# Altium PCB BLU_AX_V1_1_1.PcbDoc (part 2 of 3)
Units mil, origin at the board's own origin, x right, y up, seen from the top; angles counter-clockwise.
Board outline 2623.2 x 4215 mil, 6 copper layers (Top Layer, GND1, PWR, Signal Inner, GND2, Bottom Layer), stack 76.535 mil thick; 238 components, 119 nets, 699 pads, 786 vias.
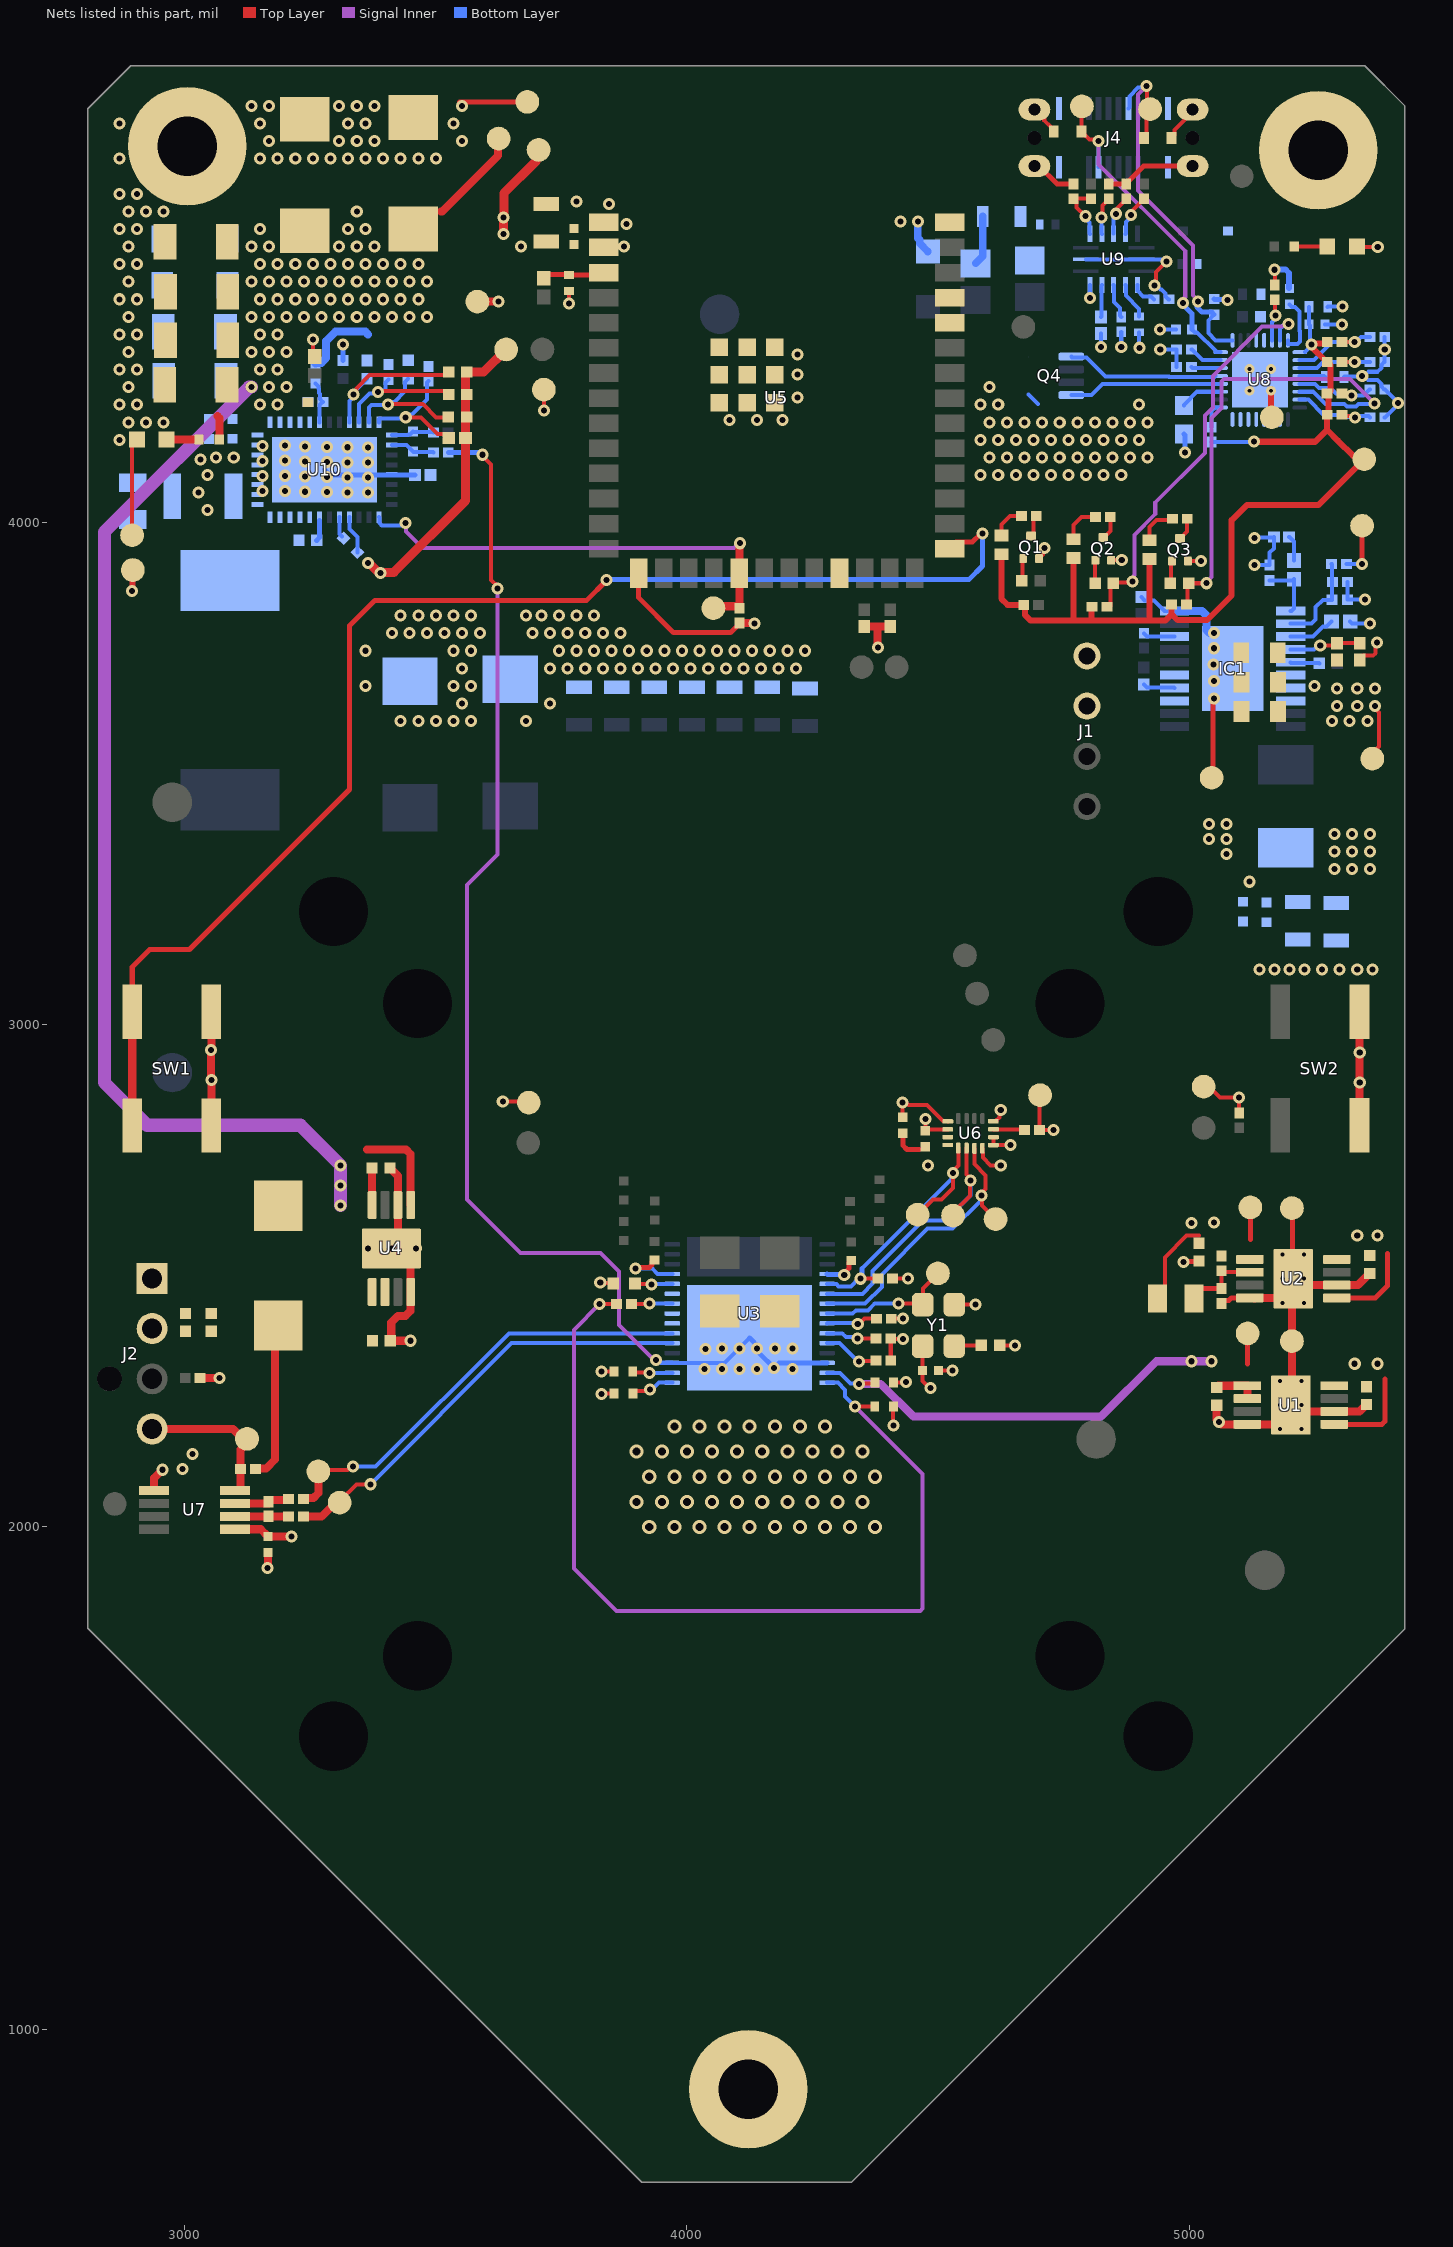
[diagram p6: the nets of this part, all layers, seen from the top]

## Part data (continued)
R4: library part CMP-x00008-3, "Fixed Resistor, Metal Glaze/thick Film, 0.1W, 2200ohm, 75V, 1% +/-Tol, 100ppm/Cel, Surface Mount, 0402", Manufacturer="KOA Speer", Package=0402, Rating=100mW, Template=KS_0402
R5 R6 R20 R29 R30 R31 R38 R80: library part CMP-x00150-1, "Fixed Resistor, Metal Glaze/thick Film, 0.1W, 10000ohm, 75V, 1% +/-Tol, 100ppm/Cel, Surface Mount, 0402"
R9 R35 R36 R37 R76 R78 R79 R81 R83: library part CMP-x00147-1, "Metal Glaze/thick Film, 0ohm, Surface Mount, 0402"
R21: library part CMP-2002-04371-1, Manufacturer="KOA Speer"
R22 R23: library part CMP-2002-03812-1, Manufacturer="KOA Speer"
R24 R27 R56 R57 R58 R62 R67: library part CMP-009-00227-1, "Fixed Resistor, Metal Glaze/thick Film, 0.1W, 10000ohm, 75V, 5% +/-Tol, 200ppm/Cel, Surface Mount, 0402", Package=0402, Rating=1/10W
R25 R26: library part CMP-x00174-1, "Fixed Resistor, Metal Glaze/thick Film, 0.1W, 100ohm, 75V, 1% +/-Tol, 100ppm/Cel, Surface Mount, 0402"
R28 R68: library part CMP-x00164-1, "Fixed Resistor, Metal Glaze/thick Film, 0.1W, 5600ohm, 75V, 1% +/-Tol, 100ppm/Cel, Surface Mount, 0402"
R32 R33 R34 R54: library part CMP-009-00229-1, "Fixed Resistor, Metal Glaze/thick Film, 0.1W, 23200ohm, 75V, 1% +/-Tol, 100ppm/Cel, Surface Mount, 0402", Package=0402, Rating=1/10W
R39: library part CMP-2002-04376-1, Manufacturer="KOA Speer", Part Number=RK73H1ETTP33R2F
R40 R43 R48 R49 R50 R51 R59 R60 R64 R65 R66: library part CMP-x00162-1, "Fixed Resistor, Metal Glaze/thick Film, 0.1W, 100000ohm, 75V, 1% +/-Tol, 100ppm/Cel, Surface Mount, 0402"
R41: library part CMP-2002-04506-1, Manufacturer="KOA Speer"
R42: library part CMP-2002-04318-1, Manufacturer="KOA Speer"
R44: library part CMP-2002-04177-1, Manufacturer="KOA Speer"
R47 R61: library part CMP-x00015-3, "Fixed Resistor, Thin Film, 0.063W, 1000ohm, 50V, 0.1% +/-Tol, 25ppm/Cel, Surface Mount, 0402", Manufacturer=Panasonic, Package=0402, Rating=63mW, Template=PS_0402
R52 R55: library part CMP-x00172-1, "Fixed Resistor, Metal Glaze/thick Film, 0.1W, 4990ohm, 75V, 1% +/-Tol, 100ppm/Cel, Surface Mount, 0402"
R53: library part CMP-x00173-1, "Fixed Resistor, Metal Glaze/thick Film, 0.1W, 118000ohm, 75V, 1% +/-Tol, 100ppm/Cel, Surface Mount, 0402"
R63: library part CMP-x00167-1, "Fixed Resistor, Metal Glaze/thick Film, 0.25W, 3.6ohm, 150V, 1% +/-Tol, 200ppm/Cel, Surface Mount, 0805"
R69: library part CMP-2002-03957-1, Manufacturer="KOA Speer"
R70: library part CMP-x00151-1, "BOM UPDATE 25.5K (NEW) RESISTOR FROM 11.7K (OLD) /  / NEW: RK73H1ETTP2552F"
R71: library part CMP-x00144-1, "Fixed Resistor, Metal Glaze/thick Film, 0.1W, 10ohm, 75V, 1% +/-Tol, 100ppm/Cel, Surface Mount, 0402"
R72: library part CMP-x00142-1, "Fixed Resistor, Metal Glaze/thick Film, 0.5W, 1ohm, 200V, 1% +/-Tol, 200ppm/Cel, Surface Mount, 1210", Manufacturer="KOA Speer", Package=1210, Template=KO_0402
R73: library part CMP-2002-04015-1, "BOM UPDATE 4.32K (NEW) RESISTOR FROM 37.4K (OLD) /  / NEW: RK73H1ETTP4321F", Manufacturer="KOA Speer", Part Number=RK73H1ETTP3741F
R74 R77: library part CMP-x00154-1, "Fixed Resistor, Metal Glaze/thick Film, 0.1W, 49.9ohm, 75V, 1% +/-Tol, 100ppm/Cel, Surface Mount, 0402"
R75: library part CMP-2002-04539-1, Manufacturer="KOA Speer"
R82: library part CMP-x00145-1, "Fixed Resistor, Metal Glaze/thick Film, 0.1W, 68100ohm, 75V, 1% +/-Tol, 100ppm/Cel, Surface Mount, 0402"
R84: library part CMP-x00149-1, "Fixed Resistor, Metal Glaze/thick Film, 0.1W, 14700ohm, 75V, 1% +/-Tol, 100ppm/Cel, Surface Mount, 0402"
RJ1: library part CMP-009-00121-2, Max Operating Temperature=155°C, Min Operating Temperature=-55°C
SW1 SW2: library part CMP-011-00029-1, "No Description Available", Mfr_Name=Omron
TP1 TP2 TP12 TP13 TP14 TP16 TP17 TP18 TP19 TP20 TP21 TP22 TP23 TP24 TP25 TP26 TP27 TP28 TP29 TP30 TP31 TP32 TP33 TP34 TP35 TP36 TP37 TP38 TP39 TP40: library part CMP-001-0086-3, "digital shovel test point"
TP3 TP4 TP5 TP6 TP7 TP8 TP9 TP10 TP11 TP15 TP41: library part CMP-001-0086-4, "digital shovel test point"
TVS3 TVS4: library part CMP-x00209-4, "Trans Voltage Suppressor Diode, 180W, 5V V(RWM), Unidirectional, 1 Element, Silicon", Manufacturer=Nexperia, Package=SOD_523_2, Template=NX_SOD_523_2
U1: library part CMP-x00161-1, "Adjustable- and fixed-output, 1-A, 16-V, positive-voltage low-dropout (LDO) linear regulator 8-HVSSOP -40 to 125"
U2: library part CMP-x00158-1, "Adjustable Positive Standard Regulator, 0.8V Min, 13.6V Max, PDSO8"
U3: library part CMP-x00104-5, "BCM1370 Miner Chip", Manufacturer=Bitmain, Package=QFN32, Template=BM_QFN32
U4: library part CMP-x00161-4, "Adjustable- and fixed-output, 1-A, 16-V, positive-voltage low-dropout (LDO) linear regulator 8-HVSSOP -40 to 125", Manufacturer=TI, Package=HVSSOP, Template=TI_HVSSOP
U5: library part CMP-226-000000-01-A-2, "No Description Available", Mfr_Name="Espressif Systems"
U6: library part CMP-x00133-2, "74AVC4T774 - 4-bit dual supply translating transceiver; 3-state", Manufacturer=Nexperia, Package=XQFN_16, Template=NX_XQFN_16
U7: library part CMP-x00137-1, "Serial Switch/Digital Sensor, 11 Bit(s), 2Cel, Square, Surface Mount", Manufacturer=Microchip, Package=TSSOP_8, Template=MC_TSSOP_8
U8: library part CMP-x00105-1, "Sink-only USB Type-C® and USB Power Delivery (PD) controller with no firmware development required 32-VQFN -40 to 125", Manufacturer="Texas Instruments", Package=32-VQFN, Template=TI_VQFN_32
U9: library part CMP-x00113-1, "28V/6A Efuse With True Rcb & Frs", Manufacturer=Littelfuse, Package=QFN_16, Template=LF_QFN_16
U10: library part CMP-x00141-6, "Switching Regulator, Current-mode, 40A, 1500kHz Switching Freq-Max, PQCC40"
Y1: library part CMP-x00169-1, "Xtal Osc Xo 25MHZ 1.2V Cmos SMD"

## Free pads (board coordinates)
  round 236.22 / inner round 0 / far side round 236.22 hole 118.11: 12(3005,4750) 12(5257.08,4741.78)
  round 236.22 hole 118.11: 12(4122.25,880.36)
  round 60 hole 137.8: 13(3296.18,1583.27) 13(3296.18,3225.75) 13(3463.5,1743.46) 13(3463.5,3042.68) 13(4762.72,1743.46) 13(4762.72,3042.68) 13(4938.67,1583.26) 13(4938.67,3225.75)

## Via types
v1: diameter 24, hole 12, Top Layer to Bottom Layer, tented both sides, 623 vias
v2: diameter 28, hole 16, Top Layer to Bottom Layer, 146 vias
v3: diameter 19.68, hole 7.87, Top Layer to Bottom Layer, 16 vias
v4: diameter 24, hole 12, Top Layer to Bottom Layer, 1 vias

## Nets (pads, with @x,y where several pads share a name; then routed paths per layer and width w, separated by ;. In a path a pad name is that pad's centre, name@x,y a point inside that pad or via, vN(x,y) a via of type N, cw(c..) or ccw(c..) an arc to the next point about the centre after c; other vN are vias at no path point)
0V8_REF: C1.2 C6.1 TP13.1 U1.1 U1.2 U3.14 | length 1029.4
  Top Layer w8: v1(4343.09,2285.07) 4344,2285.98 4372.75,2285.98 C6.1@4374.39,2287.63
  Top Layer w10: 5115.97,2324.45 5115.97,2384.79 TP13.1@5116.67,2385.49
  Top Layer w16: C1.2@5055,2277.8 5055.08,2277.8 5058.46,2281.18 U1.1@5116.17,2281.18 U1.2@5116.17,2255.59
  Signal Inner w16: v1(4343.09,2285.07) 4385.65,2285.07 4450.94,2219.78 4824.78,2219.78 4935,2330 v1(5005,2330) v1(5045,2330)
  Bottom Layer w8: U3.14@4279.17,2306.89 4305.02,2306.89 4326,2285.92 4342.25,2285.92 v1(4343.09,2285.07)
1V2: C4.2 C5.1 C7.1 C10.1 C19.2 R1.2 R3.2 R9.2 TP14.1 U2.1 U3.15 U6.5 U6.6 U6.14 Y1.4 | length 2373.9
  Top Layer w8: v1(3826.3,2443.7) R3.2@3860.01,2443.7 R3.2@3858.7,2445 ; v1(4334.7,2240) 4334.8,2240.09 4373.93,2240.09 C7.1@4374.02,2240.19 ; C10.1@4469.31,2311.47 4469.31,2359.86 Y1.4@4469.46,2360 ; C10.1@4469.36,2311.47 4469.36,2290.64 4483.34,2276.66 v1(4485.39,2276.66) ; C19.2@4474.73,2788.94 4474.81,2789.02 4474.81,2812.68 v1(4474.88,2812.76) ; C19.2@4475.89,2787.78 4479.99,2791.89 U6.14@4519.57,2791.89 ; U6.6@4610.5,2776.4 4610.42,2776.32 4610.42,2760.75 U6.5@4610.75,2760.42 ; U6.5@4610.56,2760.2 v1@4644.37,2760.2 ; R9.2@4622.98,2361.58 v1(4653.42,2361.58) ; C5.1@4937.17,2455 4951.84,2469.68 4951.84,2536.84 4995,2580 5020,2580
  Top Layer w10: 5122.03,2572.97 TP14.1@5122.03,2636.55
  Signal Inner w8: v1(3826.3,2443.7) 3775,2392.39 3775,1917.43 3859.38,1833.05 4464.72,1833.05 4469.4,1837.73 4469.4,2105.3 v1(4334.7,2240)
  Bottom Layer w8: U3.15@4279.17,2287.2 4300.83,2287.2 4315,2273.03 4315,2260 4335,2240 v1(4334.7,2240) v1@4334.41,2240
  other v1: 5005,2605 5049.96,2606.23 4644.58,2760.42
3V3_ESP: C2.2 C3.2 C16.1 C17.1 C20.1 C21.1 C27.1 C28.1 C29.1 C30.1 C31.2 J1.2 L1.2 R20.2 R22.2 R23.2 R28.2 R38.2 R80.2 TP1.1 TP4.1 U1.5 U1.8 U2.5 U2.8 U5.2 U5.15 U6.13 U7.1 | length 1443.7
  Top Layer w8: v1(4428.99,2845.25) 4432.05,2842.18 4439.74,2842.18 4441.67,2840.25 4477.8,2840.25 4509.97,2808.08 4519.4,2808.08 U6.13@4519.73,2807.75 ; v1@4429.49,2844.74 4429.49,2816.34 C20.1@4430,2815.83 ; TP1.1@5029.17,2876.87 5039.79,2876.87 5061.76,2854.9 v1(5099.88,2854.9) 5099.94,2854.84 5099.94,2824.59 R20.2@5100,2824.53
  Top Layer w10: U5.15@3903.94,3899.84 3903.94,3850.63 3973.08,3781.49 4087.24,3781.49 4105,3799.25 R80.2@4105,3800.24 ; R80.2@4105,3799.85 4115,3799.85 ; U1.5@5289.4,2204.41 5384.14,2204.41 5390,2210.27 5390,2295 ; U2.5@5294.36,2456.02 5371.02,2456.02 5395,2480 5395,2545
  Top Layer w16: R28.2@3030.53,2296.27 v1(3068.73,2296.27) ; U7.1@3100.02,1995.4 3151.25,1995.4 3164.44,1982.21 3164.44,1982.13 C21.1@3165.74,1980.91 C21.1@3165.74,1980.91 v1(3212.26,1980.91) ; 4115,3799.85 4133.85,3799.85 v1(4134.24,3799.46) ; R22.2@4353.31,3793.27 4383.21,3793.27 R23.2@4405,3793.27 ; 4379.92,3793.27 4379.92,3792.74 4379.69,3792.51 4379.69,3752.22 v1(4380.67,3751.24)
  Top Layer w18: v1(3635,4575) 3634.7,4575.3 3634.7,4607.19 v1(3634.4,4607.49) 3635.55,4608.64 3635.55,4655.93 3699,4719.39 3699,4736.9 TP4.1@3704.6,4742.5
  Bottom Layer w8: C31.2@5315.49,3846.72 v1(5350.68,3846.72) ; C31.2@5315.49,3846.72 R38.2@5315.53,3882.04
  other v1: 5330,2325 5375,2325 5335,2580 5375,2580 5120,3285 5290,3310 5325,3310 5360,3310 5075,3340 5290,3345 5325,3345 5360,3345 5040,3370 5075,3370 5290,3380 5325,3380 5360,3380 5040,3400 5075,3400 3670,4550 3875,4550
3V3_IN: C12.2 C34.1 C35.1 C36.1 C41.1 C53.2 C54.2 C56.1 C57.1 C58.1 C59.1 C60.2 C61.2 C62.2 C63.2 C64.1 C65.1 IC1.6 IC1.7 IC1.8 Q4.5 R40.2 R47.2 R70.2 R71.2 TP2.1 TP35.1 U4.5 U4.8 U8.19 U10.21 U10.22 U10.23 U10.24 U10.25 | length 2861
  Top Layer w8: TP35.1@5365,3530 5365,3540.62 5378.4,3554.02 5378.4,3622.31 5370,3630.71 v1(5370,3635)
  Top Layer w16: 3065,4212.4 3068.7,4208.7 R47.2@3068.7,4165.75 ; 3362.47,2751.67 3440.55,2751.67 3449.92,2742.29 U4.5@3449.92,2641.17 ; C12.2@3372.99,2714.79 3373.07,2714.71 U4.8@3373.15,2641.17 U4.8@3373.15,2641.17 ; 3510,4620 3512.74,4620 3623.7,4730.96 3623.7,4761.88 TP2.1@3625.91,4764.09
  Signal Inner w26: v1(3132.5,4270) 3128.28,4270 2840,3981.72 2840,2885 2925,2800 3230,2800 v1(3310,2720) v1(3310,2640)
  Bottom Layer w8: Q4.5@4679.98,4255.21 4699.17,4236.02 ; C41.1@4990,4233.61 4990,4234.53 5016.31,4260.84 U8.19@5063,4260.84
  other v1: 3310,2680 5285,3605 5320,3605 5355,3605 5295,3635 5335,3635 5295,3670 5335,3670 5370,3670 5250,3675 4585,4095 4620,4095 4655,4095 4690,4095 4725,4095 4760,4095 4795,4095 4830,4095 4865,4095 4602.5,4130 4637.5,4130 4672.5,4130 4707.5,4130 4742.5,4130 4777.5,4130 4812.5,4130 4847.5,4130 4882.5,4130 4917.5,4130 4585,4165 4620,4165 4655,4165 4690,4165 4725,4165 4760,4165 4795,4165 4830,4165 4865,4165 4900,4165 4602.5,4200 4637.5,4200 4672.5,4200 4707.5,4200 4742.5,4200 4777.5,4200 4812.5,4200 4847.5,4200 4882.5,4200 4917.5,4200 3150,4235 3185,4235 4585,4235 4620,4235 4900,4235 3167.5,4270 3202.5,4270 4602.5,4270 3150,4305 3185,4305 3132.5,4340 3167.5,4340 3202.5,4340 3150,4375 3185,4375 3132.5,4410 3167.5,4410 3202.5,4410 3237.5,4410 3272.5,4410 3307.5,4410 3342.5,4410 3377.5,4410 3412.5,4410 3447.5,4410 3482.5,4410 3150,4445 3185,4445 3220,4445 3255,4445 3290,4445 3325,4445 3360,4445 3395,4445 3430,4445 3465,4445 3132.5,4480 3167.5,4480 3202.5,4480 3237.5,4480 3272.5,4480 3307.5,4480 3342.5,4480 3377.5,4480 3412.5,4480 3447.5,4480 3482.5,4480 3150,4515 3185,4515 3220,4515 3255,4515 3290,4515 3325,4515 3360,4515 3395,4515 3430,4515 3465,4515 3132.5,4550 3167.5,4550 3307.5,4550 3342.5,4550 3377.5,4550 3150,4585 3325,4585 3360,4585 3342.5,4620
3V3_PD: C44.1 C45.1 D1.2 D2.2 D3.2 R29.1 R30.1 R31.1 R48.2 R49.2 R50.2 R51.2 R62.2 TP31.1 U8.1 | length 2020.2
  Top Layer w12: D1.2@4626.25,3937.12 4626.25,3848.75 4638.85,3836.15 R29.1@4670.74,3836.15 4673.15,3833.73 4673.15,3816.44 4684.59,3805 4769.76,3805 4775,3805 ; D2.2@4769.76,3929.7 4769.76,3810.24 4775,3805 ; 4806.21,3805 R31.1@4806.21,3830.5 ; 4810,3805 4775,3805 ; 4813.42,3805.16 4920.16,3805.16 ; D3.2@4921.42,3927.8 4921.42,3806.42 4920.16,3805.16 ; 4965.01,3818.02 4965.35,3817.68 ; 4965.01,3820.01 R30.1@4965.01,3836.8 ; v1(5129.64,4161.72) 5130.11,4161.24 5251.24,4161.24 5275.24,4185.24 R51.2@5275.24,4215 5277.68,4217.44 5277.68,4255.3 R50.2@5275.95,4257.03 ; R50.2@5274.97,4257.03 R50.2@5275.95,4257.03 ; 5275.24,4184.74 5296.36,4163.61 5326.82,4133.15 5342.18,4133.15 TP31.1@5348.92,4126.41 5257.51,4035 5115,4035 5085,4005 5085,3855 5036.17,3806.17 4976.86,3806.17 4965.35,3817.68 ; R49.2@5275.24,4320.12 5274.13,4320.12 5243.57,4350.68 v1(5243.57,4354.78) 5246.18,4357.39 5272.63,4357.39 R48.2@5275.24,4360 ; R49.2@5276.22,4320 5281.65,4314.57 5281.65,4262.73 R50.2@5275.95,4257.03 ; 4920.16,3805.16 4920,3805 4952.67,3805 4965.35,3817.68
  Bottom Layer w8: R62.2@5045,4160.47 5045.62,4161.1 5129.02,4161.1 v1(5129.64,4161.72) ; U8.1@5231.25,4339.65 5243.57,4351.97 v1(5243.57,4354.78) 5241.37,4356.98 5241.37,4392.8 C45.1@5239.17,4395 5239,4395.16 5239,4429.92 C44.1@5238.84,4430.09
3V3_PD_BATT: C49.1 U8.32 | length 118.8
  Bottom Layer w8: U8.32@5196.86,4363.2 5196.86,4356.35 5196.93,4356.28 5216.15,4356.28 5220.84,4360.97 5220.84,4381.38 5220.45,4381.76 5220.45,4420.33 5211,4429.78 5205.22,4429.78 C49.1@5200,4435
AGND: C67.2 R81.1 R82.1 R83.1 R84.1 RJ1.1 | length 152.8
  Bottom Layer w16: C67.2@3260.5,4316.7 3262.34,4318.55 3272.16,4318.55 3281.53,4327.92 3281.53,4361.53 3300.42,4380.42 3359.58,4380.42 3365,4375
BAD_INPUT: R30.2 R37.1 U8.6 | length 983.2
  Top Layer w8: R30.2@4994.98,3836.8 4997.19,3839.02 4997.19,3877.18 4999.45,3879.44 5034.97,3879.44 v1(5035.02,3879.49)
  Signal Inner w8: v1(5035.02,3879.49) 5035.02,3882.05 5045.14,3892.18 5045.14,4208.4 5065,4228.26 5065,4281.18 5069.69,4285.86 5320.75,4285.86 v1(5368.95,4237.66)
  Bottom Layer w8: U8.6@5220.48,4260.84 5247.26,4260.84 5271.42,4236.68 5309.12,4236.68 5314.33,4231.47 5332.14,4231.47 5337.36,4236.68 5367.98,4236.68 v1(5368.95,4237.66)
BOOT_PIN: SW1.1 SW1.2 U5.27 | length 2680.8
  Top Layer w10: SW1.2@2895.35,3026.02 2905,3035.67 2895.35,3045.32 2895.35,3115.35 2930,3150 3009.27,3150 3328.08,3468.81 3328.08,3794.87 3378.64,3845.43 3800.43,3845.43 3840,3885 v1(3840,3885.61) ; U5.27@4523.43,3949.06 4535.93,3961.56 4568.39,3961.56 4584.94,3978.1 v1(4588.72,3978.1)
  Top Layer w16: SW1.1@2895.35,2799.65 SW1.2@2895.35,3026.02
  Bottom Layer w10: v1(3840,3885.61) 3841.53,3887.14 4562.14,3887.14 4588.72,3913.72 v1(4588.72,3978.1)
BP1V5: C78.2 R75.1 R76.2 R78.2 R79.2 TP38.1 U10.4 | length 692.9
  Top Layer w18: v1(3365,3920) 3366.62,3920 3385.48,3901.15 3388.85,3901.15 v1(3390,3900) 3391.15,3901.15 3416.15,3901.15 3559.25,4044.25 R75.1@3559.25,4168.52 3559.25,4297.91 3561.59,4300.25 R76.2@3561.89,4300.25 3595.25,4300.25 TP38.1@3640,4345
  Bottom Layer w8: U10.4@3327.6,4011.02 3327.6,3987.4 3343.92,3971.08 C78.2@3343.92,3941.08
BST: C26.2 IC1.5 | length 57.7
  Bottom Layer w8: IC1.5@5202.53,3722.06 5203.56,3721.03 5258.37,3721.03 C26.2@5259.4,3720
CC1: C46.1 J4.A5 TP29.1 TVS3.1 U8.24 | length 679.5
  Top Layer w8: TP29.1@4786.71,4829.31 4786.16,4828.76 4786.16,4779.64 TVS3.1@4785.61,4779.09 4785.61,4777.12 4791.45,4771.28 4793.42,4771.28 4801.73,4762.97 4817.03,4762.97 v1(4820.09,4759.91)
  Signal Inner w8: v1(4820.09,4759.91) 4820.09,4713.76 4992.47,4541.37 4992.47,4449.92 4991.15,4448.6 4991.15,4440.3 v1(4988.09,4437.23)
  Bottom Layer w8: J4.A5@4820.09,4708.04 v1(4820.09,4759.91) ; C46.1@5005.75,4385 5011.98,4378.76 5016.26,4378.76 5052.24,4342.78 5052.24,4339.65 5052.3,4339.58 U8.24@5063,4339.58
  Bottom Layer w10: v1(4988.09,4437.23) 4988.09,4434.11 5005.62,4416.58 5005.62,4385.13 C46.1@5005.75,4385
CC2: C47.1 J4.B5 TP30.1 TVS4.1 U8.25 | length 812.3
  Top Layer w8: TVS4.1@4909.97,4766.34 4915.74,4772.12 4915.74,4817.2 TP30.1@4922.34,4823.79 4916.74,4829.39 4916.74,4868.26 v1(4915,4870)
  Signal Inner w8: v1(4915,4870) 4915,4868.76 4898.65,4852.41 4898.65,4661.35 5007.9,4552.1 5007.9,4453.01 5017.45,4443.45 v1(5017.45,4440.15)
  Bottom Layer w8: J4.B5@4879.15,4824.97 4881.05,4826.87 4881.05,4849.16 4898.82,4866.94 4911.94,4866.94 v1(4915,4870) ; C47.1@5050,4414.25 5038.88,4403.14 5038.88,4377.43 5053.11,4363.2 U8.25@5086.63,4363.2
  Bottom Layer w10: v1(5017.45,4440.15) 5015.82,4438.52 5015.82,4429.18 5025.51,4419.49 5044.76,4419.49 C47.1@5050,4414.25
COMP: C37.2 IC1.1 R42.2 | length 116.5
  Bottom Layer w8: C37.2@5160.4,3884.76 5206.42,3884.76 R42.2@5209.09,3887.43 5209.09,3829.28 5204.23,3824.42 IC1.1@5202.53,3824.42
DBG_ACC: U8.10
DGND: C1.1 C2.1 C3.1 C4.1 C6.2 C7.2 C8.2 C9.2 C10.2 C11.1 C12.1 C13.1 C16.2 C17.2 C18.1 C19.1 C20.2 C21.2 C23.1 C24.1 C25.2 C27.2 C28.2 C29.2 C30.2 C32.2 C33.2 C34.2 C35.2 C36.2 C37.1 C38.2 C39.2 C40.2 C41.2 C42.2 C43.2 C44.2 C45.2 C46.2 C47.2 C48.2 C49.2 C51.2 C52.2 C53.1 C54.1 C56.2 C57.2 C58.2 C59.2 C60.1 C61.1 C62.1 C63.1 C64.2 C65.2 C68.2 C69.2 C70.2 C71.2 C72.2 C73.2 C74.2 C75.2 C76.2 C79.2 C80.1 C81.1 C86.2 D4.2 D5.1 D6.1 D7.2 IC1.13 IC1.14 IC1.15 IC1.20 IC1.21 J1.1 J2.1 J4.A1 J4.A12 J4.B1 J4.B12 J4.S1 J4.S2 J4.S3 J4.S4 pad.12 Q1.2 Q2.2 Q3.2 R2.1 R4.1 R5.1 R6.1 R7.1 R8.1 R24.2 R39.1 R41.1 R44.1 R52.1 R53.1 R54.1 R55.1 R56.1 R57.1 R58.1 R63.1 R64.1 R65.1 R66.1 R68.1 R69.1 R72.1 R73.1 R77.2 RJ1.2 SW1.3 SW1.4 SW2.3 SW2.4 TP3.1 TP5.1 TP6.1 TP7.1 TP8.1 TP9.1 TP10.1 TP11.1 TP15.1 TP34.1 TP41.1 TVS3.2 TVS4.2 U1.4 U1.6 U1.9 U2.4 U2.6 U2.9 U3.4 U3.13 U3.18 U3.27 U3.32 U4.4 U4.6 U4.9 U5.1 U5.40 U5.41 U5.42 U5.43 U5.44 U5.45 U5.46 U5.47 U5.48 U5.49 U6.4 U6.8 U6.15 U6.16 U7.5 U8.11 U8.12 U8.14 U8.15 U8.16 U8.28 U8.29 U8.33 U9.13 U10.13 U10.14 U10.15 U10.16 U10.17 U10.18 U10.19 U10.20 U10.37 U10.41 Y1.2 | length 8283.6
  Top Layer w8: TP5.1@2895,3975 2895,4156.2 D5.1@2904.55,4165.75 ; v1(3255,4365) 3255,4334.49 R73.1@3258.68,4330.81 ; v1(3592.5,4135.37) 3592.5,4132.72 3609.65,4115.57 3609.65,3886.38 3622.53,3873.5 v1(3622.53,3869.17) ; v1(3633.26,2847.76) TP8.1@3691.61,2847.76 ; v1@3715,4223.41 3715.07,4223.48 3715.07,4264.93 TP6.1@3715,4265 ; C18.1@3765.21,4461.55 3765.34,4461.42 3765.34,4436.95 v1(3765.47,4436.82) ; v1(3827.39,2486.41) 3828.1,2485.71 3852.64,2485.71 R4.1@3853.35,2485 ; v1(3830,2310) 3854.51,2310 C9.2@3854.67,2309.84 ; v1@3830.1,2266.12 C8.2@3854.87,2266.12 ; R8.1@4405.95,2331.64 R7.1@4405.95,2375.01 4406.42,2374.54 4429.87,2374.54 v1(4430.34,2374.07) ; R6.1@4407.02,2414.73 4407.15,2414.87 4429.87,2414.87 v1(4430,2415) ; R5.1@4409.76,2495 v1(4440,2495) ; C7.2@4411.42,2240.19 4410.49,2239.26 4410.49,2203.6 v1(4411.67,2202.42) ; C6.2@4411.8,2287.63 4412.32,2288.15 4435.72,2288.15 v1(4436.25,2288.68) ; C10.2@4501.02,2311.47 v1(4528.53,2311.47) ; Y1.2@4532.45,2442.68 v1(4574.36,2442.68) ; U6.4@4588.47,2754.21 4588.8,2753.88 4588.8,2745.65 4589.2,2745.25 4589.2,2735.66 4604.86,2720 v1(4625,2720) ; U6.8@4610.19,2808.05 4616.68,2808.05 4617.02,2808.38 4617.02,2809.96 4622.06,2815 4622.06,2827.06 v1(4625,2830) ; J4.S3@4692.14,4822.8 4692.43,4822.8 4711.66,4803.56 4711.66,4800.89 4724.65,4787.9 4724.65,4784.93 TVS3.2@4730.49,4779.09 ; Q1.2@4701.25,3928.51 4701.25,3929.49 4708.9,3937.15 4708.9,3946.78 v1(4711.96,3949.84) ; TP9.1@4703.22,2860.02 4702.65,2859.45 4702.65,2791.39 R24.2@4702.08,2790.82 v1(4729.96,2790.82) ; Q2.2@4844.95,3925.15 4845.38,3925.58 4865.58,3925.58 v1(4866.01,3926.01) ; TVS4.2@4965.09,4766.34 4970.93,4772.19 4970.93,4782.48 4990.5,4802.05 4990.5,4806.49 5006.81,4822.8 J4.S4@5007.1,4822.8 ; Q3.2@4997.74,3923.66 v1(5023.64,3923.66) ; R58.1@5170.61,4473.54 5171.39,4474.33 5171.39,4503 v1(5170.61,4503.78) ; D6.1@5334.27,4550.04 5335.09,4549.22 v1(5375.86,4549.22) ; R41.1@5340,3726.54 5340,3727.52 5347.81,3735.33 5366.66,3735.33 5371.35,3740.02 5371.35,3758.37 v1(5374.41,3761.43)
  Top Layer w10: v1@3546.81,4838.19 TP41.1@3682.24,4838.19 ; v1(3898.03,2514.31) 3900.71,2516.99 3924.97,2516.99 3930.83,2522.85 3930.83,2527.45 3934.69,2531.31 C86.2@3935.67,2531.31 ; v1(4313.37,2501.5) 4313.37,2505.28 4322.48,2514.4 4322.48,2526.49 4326.34,2530.35 C13.1@4327.32,2530.35 ; C20.2@4430,2784.17 4430,2760 4438.21,2751.79 4463.08,2751.79 ; J4.S1@4692.14,4710.2 4701.98,4710.2 4737.42,4674.76 R66.1@4770,4674.76 ; R64.1@4840,4674.76 R65.1@4875,4674.76 4875,4675.75 4909.45,4710.2 J4.S2@5007.1,4710.2 ; v1(4988.74,2527.74) 4989.57,2528.57 5019.17,2528.57 C4.1@5020,2529.4 ; TP7.1@5045,3475 5047.5,3477.5 5047.5,3647.5 v1(5050,3650) ; R2.1@5065,2446.1 5065,2446.22 5069.84,2451.06 5079.37,2451.06 5084.32,2456.02 U2.4@5121.14,2456.02 ; TP10.1@5205,2635 5206.44,2633.56 5206.44,2495.71 U2.9@5207.75,2494.4 ; TP3.1@5344.69,3994 5344.74,3993.95 5344.74,3917.39 v1(5344.8,3917.34)
  Top Layer w12: v3@5163.4,4265.98 v3(5163.4,4262.81) 5163.4,4211.6 TP34.1@5165,4210
  Top Layer w16: U7.5@2939.02,2072.17 2939.02,2097.22 v1(2955.74,2113.94) ; SW1.3@3052.84,2799.65 3052.84,2890.5 3052.37,2890.99 3052.37,2949.84 3052.83,2950.31 SW1.4@3052.83,3026.02 ; v1(3165.01,1918.68) 3165.37,1919.05 3165.37,1948.88 C21.2@3165.74,1949.24 ; C12.1@3408.59,2714.79 3408.59,2714.71 3424.33,2698.97 U4.6@3424.33,2641.17 3424.33,2567.35 v1(3411.53,2554.56) 3418.55,2554.56 3449.92,2523.19 U4.4@3449.92,2467.94 3449.06,2467.08 3449.06,2429.95 3439.69,2420.57 3424.52,2420.57 3411.14,2407.19 3411.14,2372.78 C11.1@3409.16,2370.81 v1(3449.19,2370.81) ; TP15.1@3582.78,4440.32 3624.68,4440.32 v1(3624.84,4440.16) v1@3625,4440 ; C1.1@5055,2242.2 5055,2213.78 v1(5059.69,2209.09) 5064.37,2204.41 U1.4@5116.17,2204.41 5171.42,2204.41 5202.79,2235.78 U1.9@5202.79,2242.79 5215.58,2230 U1.6@5289.4,2230 5339.39,2230 5353.22,2243.83 C2.1@5353.31,2243.83 ; U2.4@5121.14,2456.02 5129.14,2456.02 5130,2455.16 5130.86,2456.02 5176.38,2456.02 U2.9@5205,2484.64 ; v3(5224.44,2290.83) 5208.02,2290.83 5205,2293.85 TP11.1@5205,2370 U2.9@5205,2484.64 ; SW2.3@5339.3,2799.65 SW2.4@5339.3,3026.03 ; C3.1@5360,2505 5359.92,2505 5356.73,2501.82 5356.73,2501.73 5336.61,2481.61 U2.6@5294.36,2481.61 5220.55,2481.61 U2.9@5207.75,2494.4 5207.75,2487.39 U2.9@5205,2484.64
  Signal Inner w8: v1(3622.53,3869.17) 3622.53,3339.44 3561.77,3278.68 3561.77,2652.47 3668.99,2545.25 3828.26,2545.25 3864.75,2508.75 3864.75,2402.33 3934.34,2332.74 v1(3938.5,2332.74) ; v1@3827.39,2487.39 v1@3827.55,2487.55
  Bottom Layer w8: v1(3898.03,2514.31) 3930.97,2514.31 3941.12,2504.17 3970.4,2504.17 U3.27@3970.83,2503.74 ; v1(3938.5,2332.74) 3942.83,2332.74 3948.56,2327 3970.4,2327 U3.18@3970.83,2326.57 4074.59,2326.57 U3.32@4124.68,2376.67 ; v1(4802.62,4447.38) U9.13@4802.62,4473.43 ; v1(4825,4350) R69.1@4825,4376.54 ; v1(4865,4350) R68.1@4865,4380.24 ; C52.2@4900,4379.25 4900.59,4378.66 4900.59,4349.01 v1(4901.19,4348.41) ; C33.2@4905,3851.87 4911.44,3845.43 4930,3845.43 4951.01,3824.42 IC1.20@4971.19,3824.42 ; C32.2@4910,3678.13 4916.29,3671.84 4970.23,3671.84 IC1.14@4971.19,3670.88 ; v1(4941.91,4384.53) 4942.14,4384.76 4974.02,4384.76 C46.2@4974.25,4385 ; v1(4942.68,4345.17) 4942.77,4345.09 4975.15,4345.09 R56.1@4975.24,4345 R57.1@4975.24,4310 ; v1(5130.2,3969.8) 5131.11,3970.71 5168.21,3970.71 C38.2@5169.12,3971.62 5169.12,3949.12 5160.4,3940.4 C37.1@5160.4,3915.47 v1(5130.47,3915.47) ; C45.2@5270.83,4395 v1(5305,4395) ; C44.2@5276.24,4430.09 5276.72,4430.56 5305.4,4430.56 v1(5305.87,4431.04) ; C48.2@5308.7,4290 5309.52,4290.82 5343.7,4290.82 5344.52,4291.65 v1@5348.85,4291.65 ; R39.1@5313.42,3917.71 5313.6,3917.53 5344.61,3917.53 v1(5344.8,3917.34) ; R44.1@5321.03,3803.1 5324.42,3799.71 v1(5360.46,3799.71) ; v1(5344.95,4292.07) 5348.43,4292.07 v1@5348.85,4291.65 ; R55.1@5389.76,4210 5390.75,4210 5416.51,4235.77 v1(5416.51,4238.01) 5416.51,4239.23 5390.75,4265 R54.1@5389.76,4265 5388.78,4265 5382.94,4270.84 5382.94,4276.4 5375,4284.34 5356.15,4284.34 v1@5348.85,4291.65 ; R52.1@5389.76,4370 v1(5389.76,4345) R53.1@5389.76,4320 5388.78,4320 5382.94,4314.16 5382.94,4308.6 5375,4300.66 5357.86,4300.66 v1@5348.85,4291.65
  Bottom Layer w10: U10.41@3278.38,4105.51 3288.65,4095.24 RJ1.2@3458.15,4095.24 ; C76.2@3315,4322.8 v1(3315,4354.92) ; R77.2@3524.76,4140 3584.08,4140 3588.71,4135.37 v1(3592.5,4135.37) ; U3.32@4124.68,2376.67 4143.18,2358.18 4143.18,2347.05 v1(4173.75,2316.48) 4183.85,2326.57 U3.13@4279.17,2326.57 ; U3.4@4279.17,2503.74 4279.74,2503.17 4311.69,2503.17 v1(4313.37,2501.5) ; C41.2@4990,4176.39 4991.99,4174.4 v1(4991.99,4140) ; C47.2@5050,4445.75 5051.01,4444.73 5075.27,4444.73 v1(5076.29,4443.72)
  Bottom Layer w12: v1@5170.17,4504.42 5192.14,4504.42 5199.17,4497.39 C49.2@5199.17,4467.41
  Bottom Layer w15: v1(4460,4600) 4460,4566.92 4463.88,4563.04 4463.88,4556.24 D7.2@4480,4540.12
  Bottom Layer w16: IC1.20@4971.19,3824.42 5025.58,3824.42 5034.95,3815.05 5034.95,3785.91 5040.86,3780 v1(5050,3780)
  other v1: 2995,2115 3015,2145 3830,2265 4035,2315 4070,2315 4105,2315 4140,2315 4210,2315 4070,2355 4105,2355 4140,2355 4175,2355 4210,2355 3365,2555 3460,2555 4480,2720 5340,2885 3052.85,2890.51 5340,2945 3051.89,2950.31 5140,3110 5170,3110 5200,3110 5230,3110 5265,3110 5300,3110 5335,3110 5365,3110 3430,3605 3465,3605 3500,3605 3535,3605 3570,3605 3679.92,3605 3552.5,3640 3727.5,3640 3360,3675 3535,3675 3570,3675 5050,3685 3552.5,3710 3727.5,3710 3762.5,3710 3797.5,3710 3832.5,3710 3867.5,3710 3902.5,3710 3937.5,3710 3972.5,3710 4007.5,3710 4042.5,3710 4077.5,3710 4112.5,3710 4147.5,3710 4182.5,3710 4217.5,3710 5048.94,3717.97 3360,3745 3535,3745 3570,3745 3745,3745 3780,3745 3815,3745 3850,3745 3885,3745 3920,3745 3955,3745 3990,3745 4025,3745 4060,3745 4095,3745 4130,3745 4165,3745 4200,3745 4235,3745 5050,3750 3412.5,3780 3447.5,3780 3482.5,3780 3517.5,3780 3552.5,3780 3587.5,3780 3692.5,3780 3727.5,3780 3762.5,3780 3797.5,3780 3832.5,3780 3867.5,3780 3430,3815 3465,3815 3500,3815 3535,3815 3570,3815 3679.92,3815 3710,3815 3745,3815 3780,3815 3815,3815 3045,4025 3027.5,4060 3324.39,4060.27 3365,4060 3283.63,4061.22 3239.78,4061.67 3154.36,4063.07 3199.14,4063.5 3324.39,4090.27 3365,4090 3283.63,4091.22 3239.78,4091.67 3154.36,4093.07 3199.14,4093.5 3045,4095 3324.39,4120.27 3365,4120 3283.63,4121.22 3239.78,4121.67 3154.36,4123.07 3199.14,4123.5 3031.57,4125.93 3062.5,4130 3097.5,4130 3324.39,4150.27 3365,4150 3283.63,4151.22 3239.78,4151.67 3154.36,4153.07 3199.14,4153.5 2870,4165 2887.5,4200 2922.5,4200 2957.5,4200 4085,4205 4140,4205 4190,4205 3715.13,4223.28 2870,4235 2905,4235 4219.82,4249.59 2887.5,4270 4220,4295 2870,4305 2905,4305 4220.31,4335.43 2887.5,4340 2870,4375 2905,4375 2887.5,4410 2870,4445 2905,4445 2887.5,4480 2870,4515 2905,4515 2887.5,4550 2870,4585 2905,4585 3880,4595 4425,4600 2887.5,4620 2922.5,4620 2957.5,4620 3845,4635 3780,4640 2870,4655 2905,4655 2870,4725 3150,4725 3185,4725 3220,4725 3255,4725 3290,4725 3325,4725 3360,4725 3395,4725 3430,4725 3465,4725 3500,4725 3167.5,4760 3307.5,4760 3342.5,4760 3377.5,4760 3552.5,4760 2870,4795 3150,4795 3325,4795 3360,4795 3535,4795 3132.5,4830 3167.5,4830 3307.5,4830 3342.5,4830 3377.5,4830 3552.5,4830
  other v2: 3925,2000 3975,2000 4025,2000 4075,2000 4125,2000 4175,2000 4225,2000 4275,2000 4325,2000 4375,2000 3900,2050 3950,2050 4000,2050 4050,2050 4100,2050 4150,2050 4200,2050 4250,2050 4300,2050 4350,2050 3925,2100 3975,2100 4025,2100 4075,2100 4125,2100 4175,2100 4225,2100 4275,2100 4325,2100 4375,2100 3900,2150 3950,2150 4000,2150 4050,2150 4100,2150 4150,2150 4200,2150 4250,2150 4300,2150 4350,2150 3975,2200 4025,2200 4075,2200 4125,2200 4175,2200 4225,2200 4275,2200
  other v3: 5181.13,2194.76 5224.44,2194.76 5181.13,2242.79 5224.44,2242.79 5181.13,2290.83 5186.1,2446.37 5229.4,2446.37 5186.1,2494.4 5229.4,2494.4 5186.1,2542.43 5229.4,2542.43 5120.09,4262.81 5120.09,4306.12 5163.4,4306.12
  other v4: 4036.99,2354.76
EN: IC1.4 R40.1 R41.2 | length 142.6
  Top Layer w8: v1(5261.34,3755.87) 5290.87,3755.87 R40.1@5295,3760 R41.2@5340,3760
  Bottom Layer w8: IC1.4@5202.53,3747.65 5248.79,3747.65 5257.01,3755.87 v1(5261.34,3755.87)
FAULT_IN: R62.1 U8.17 | length 53.1
  Bottom Layer w8: R62.1@5045,4190 5045,4222.04 5052.3,4229.35 U8.17@5063,4229.35
FB: C31.1 IC1.2 R38.1 R39.2 | length 188.1
  Bottom Layer w8: IC1.2@5202.53,3798.83 5243.83,3798.83 5251.92,3806.92 5251.92,3831.92 5266.45,3846.45 5284.52,3846.45 C31.1@5284.78,3846.72 5284.34,3847.16 5284.34,3917.27 R39.2@5283.89,3917.71
FS: C11.2 C23.2 C24.2 C25.1 J2.2 R27.2 U4.1 U4.2 | length 316.7
  Top Layer w16: R27.2@3140.48,2115.68 3141.52,2116.72 3162.06,2116.72 3180,2134.66 3180,2394.81 C25.1@3186.48,2401.28
FSW: IC1.3 R44.2 | length 93.5
  Bottom Layer w8: IC1.3@5202.53,3773.24 5246.79,3773.24 5266.86,3793.32 5273.85,3793.32 R44.2@5283.63,3803.1
LDO_1V5_PD: C48.1 U8.4 | length 51.8
  Bottom Layer w8: U8.4@5220.48,4292.34 U8.4@5220.48,4292.34 5269.02,4292.28 C48.1@5271.3,4290
MINER_CLK: TP19.1 U3.8 Y1.3 | length 274.3
  Top Layer w8: v1(4421.44,2444.99) 4467.15,2444.99 Y1.3@4469.46,2442.68 4469.73,2442.95 4469.73,2474.73 TP19.1@4500,2505
  Bottom Layer w8: U3.8@4279.45,2424.72 4330.09,2424.72 4336.78,2431.41 4360.5,2431.41 4374.09,2445 v1(4421.44,2444.99)
MINER_RST: R5.2 TP16.1 U3.5 U6.1 | length 573
  Top Layer w8: v1(4345.68,2494.34) 4346.01,2494.67 4379.91,2494.67 R5.2@4380.24,2495 ; TP16.1@4459.55,2621.89 4489.86,2652.2 4507.2,2652.2 4530,2675 v1(4530,2705) 4530,2709.33 4540.43,2719.76 U6.1@4540.43,2754.52
  Bottom Layer w8: U3.5@4279.17,2484.06 4279.6,2483.63 4297.72,2483.63 4302.24,2479.11 4326.97,2479.11 4342.2,2494.34 v1(4345.68,2494.34) ; 4348.36,2514.4 4526.94,2692.97 4526.94,2701.94 v1(4530,2705)
  Bottom Layer w10: v1(4345.68,2494.34) 4348.36,2497.02 4348.36,2514.4
MINER_RX: TP18.1 U3.7 U6.3 | length 582
  Top Layer w8: U6.3@4572.49,2753.9 4572.49,2722.51 4595,2700 4595,2672.83 4586.5,2664.33 v1(4586.5,2660) ; v1@4585,2660 4588.06,2656.94 4588.06,2639.84 TP18.1@4614.71,2613.2
  Bottom Layer w8: U3.7@4279.17,2444.68 4322.72,2444.68 4322.95,2444.91 4354.91,2444.91 4388.08,2478.08 4388.08,2503.08 4479.01,2594.01 4529.01,2594.01 4583.44,2648.44 4583.44,2656.94 v1(4586.5,2660)
MINER_TEMP_N: R26.1 TP26.1 U3.21 | length 896.6
  Top Layer w8: TP26.1@3265.86,2110.47 3268.61,2113.22 3323.89,2113.22 3330.67,2120 v1(3335,2120)
  Top Layer w16: R26.1@3236.16,2055.94 3238.01,2057.79 3256.49,2057.79 3265.86,2067.16 TP26.1@3265.86,2110.47
  Bottom Layer w8: v1(3335,2120) 3380,2120 3645.63,2385.63 U3.21@3970.83,2385.63
MINER_TEMP_P: R25.1 TP25.1 U3.20 | length 879.5
  Top Layer w8: TP25.1@3308.43,2048.34 3308.43,2051.7 3341.73,2085 v1(3370,2085)
  Top Layer w16: R25.1@3236.16,2020.94 3272.59,2020.94 3299.98,2048.34 TP25.1@3308.43,2048.34
  Bottom Layer w8: v1(3370,2085) 3650.94,2365.94 U3.20@3970.83,2365.94
MINER_TX: TP17.1 U3.6 U6.2 | length 564
  Top Layer w8: TP17.1@4530,2620 4530,2625.93 4563.5,2659.43 4563.5,2688.5 v1(4565,2690) 4565,2694.33 4556.97,2702.36 U6.2@4556.97,2754.37
  Bottom Layer w8: U3.6@4279.17,2464.37 4349.92,2464.37 4370,2484.45 4370,2510 4470.46,2610.46 4515.46,2610.46 4565,2660 v1(4565,2690)
MOUT: R67.1 U9.7 U9.15 | length 263.5
  Top Layer w8: v1(4930.93,4472.34) 4933.99,4475.4 4933.99,4499.06 v1@4954.93,4520
  Bottom Layer w8: U9.15@4794.36,4524.43 U9.7@4905.36,4524.43 4950.57,4524.43 v1(4955,4520) ; v1(4930.93,4472.34) 4935.26,4472.34 4943.26,4464.34 4945,4464.34 4952.94,4456.4 4952.94,4450.84 4958.78,4445 R67.1@4959.76,4445
NetC5_2: C5.2 R1.1 R2.2 U2.2 | length 159.3
  Top Layer w8: R2.2@5065,2474.76 R1.1@5065,2510.24 5067.79,2507.44 U2.2@5120.89,2507.44
  Top Layer w10: C5.2@5010,2455 5010,2461.06 5023.7,2474.76 R2.2@5065,2474.76
NetC8_1: C8.1 U3.16 | length 87.3
  Top Layer w8: C8.1@3892.28,2266.12 3896.43,2270.28 3923.66,2270.28 v1(3926.72,2273.34)
  Bottom Layer w8: v1(3926.72,2273.34) 3930.59,2273.34 3944.46,2287.2 U3.16@3970.83,2287.2
NetC9_1: C9.1 U3.17 | length 80.5
  Top Layer w8: C9.1@3892.07,2309.84 3893.84,2308.07 3923.63,2308.07 v1(3925.4,2306.3)
  Bottom Layer w8: v1(3925.4,2306.3) 3925.7,2306.6 3970.53,2306.6 U3.17@3970.83,2306.89
NetC22_1: C22.1 R26.2 U7.3 | length 113.2
  Top Layer w16: U7.3@3100.02,2046.58 C22.1@3166.4,2046.58 ; C22.1@3166.4,2046.9 3166.4,2051.69 3168.48,2053.77 3180.21,2053.77 3180.54,2054.1 3204.79,2054.1 R26.2@3206.64,2055.94
NetC22_2: C22.2 R25.2 U7.2 | length 107.1
  Top Layer w16: U7.2@3100.02,2020.99 3100.31,2021.27 3166.12,2021.27 C22.2@3166.4,2021.55 3166.7,2021.25 3206.33,2021.25 R25.2@3206.64,2020.94
NetC38_1: C38.1 R42.1 | length 51.6
  Bottom Layer w8: C38.1@5198.81,3971.62 5199.71,3971.62 5209.09,3962.23 R42.1@5209.09,3924.83
NetC50_2: C50.2 R63.2 | length 99.5
  Bottom Layer w15: C50.2@4575,4516.47 4589.24,4530.71 R63.2@4589.24,4610.05
NetC52_1: C52.1 U9.10 | length 73.9
  Bottom Layer w8: U9.10@4873.49,4473.43 4874.14,4472.78 4874.14,4452.11 4900.31,4425.94 4900.31,4411.06 C52.1@4900,4410.75
NetC55_1: C55.1 U10.7 | length 41.6
  Bottom Layer w10: C55.1@3262.8,3965 3268.03,3970.23 3268.03,4003.78 U10.7@3268.46,4004.21
NetC55_2: C55.2 C66.1 L2.1 TP33.1 U10.8 U10.9 U10.10 U10.11 U10.12 | length 42.1
  Top Layer w12: v1(2894.57,3864.37) 2895.5,3865.3 2895.5,3904.8 TP33.1@2896.43,3905.73
NetC66_2: C66.2 R72.2
NetC67_1: C67.1 R71.1 U10.26 | length 85.8
  Bottom Layer w8: C67.1@3260.5,4277.33 3266.34,4271.49 3266.34,4267.54 3267.08,4266.8 3267.08,4258.36 3268.85,4256.58 3268.85,4245.97 3274.7,4240.13 R71.1@3275.04,4240.13 ; U10.26@3268.54,4200 3268.54,4234.61 R71.1@3274.06,4240.13
NetC77_1: C77.1 R74.1 U10.33 | length 86.3
  Bottom Layer w8: U10.33@3412.24,4174.41 3436.05,4174.41 3436.12,4174.48 3444.15,4174.48 3445.32,4175.65 3448.84,4175.65 C77.1@3454.68,4181.49 3455.42,4180.75 3494.25,4180.75 R74.1@3495,4180
NetC77_2: C77.2 R77.1 U10.34 | length 89.3
  Bottom Layer w8: U10.34@3412.24,4154.72 3412.52,4155 3441.8,4155 C77.2@3454.68,4142.12 3455.74,4141.06 3494.17,4141.06 R77.1@3495.24,4140
NetC78_1: C78.1 U10.5 | length 40.1
  Bottom Layer w8: U10.5@3307.91,4011.02 3308.14,4010.8 3308.14,3977.53 C78.1@3312.75,3972.92
NetD1_1: D1.1 R32.2 | length 69
  Top Layer w8: D1.1@4626.25,3974.52 4626.25,3996.25 4643.57,4013.57 R32.2@4666.3,4013.57
NetD2_1: D2.1 R33.2 | length 75.3
  Top Layer w8: D2.1@4770,3970 4770,3980 4770,3990 4770,3995 4786.27,4011.27 R33.2@4813.59,4011.27
NetD3_1: D3.1 R34.2 | length 78.4
  Top Layer w8: D3.1@4921.42,3965.2 4921.42,3991.42 4935,4005 4964,4005 R34.2@4966.82,4007.82
NetD5_2: D5.2 R47.1 | length 64.7
  Top Layer w16: D5.2@2963.61,4165.75 R47.1@3028.35,4165.75
NetD6_2: D6.2 R61.1 | length 65.3
  Top Layer w8: R61.1@5209.92,4550.04 D6.2@5275.21,4550.04
NetQ1_1: Q1.1 R35.2 | length 45.2
  Top Layer w8: R35.2@4667.15,3884.43 4668.45,3885.73 4668.45,3927.21 Q1.1@4669.75,3928.51
NetQ1_3: Q1.3 R32.1 | length 48.1
  Top Layer w8: Q1.3@4680.17,3975.17 4686.52,3975.17 4690,3978.64 R32.1@4690,4015.45
NetQ2_1: Q2.1 R36.2 | length 45.7
  Top Layer w8: R36.2@4812.89,3879.73 4813.17,3880.01 4813.17,3924.87 Q2.1@4813.45,3925.15
NetQ2_3: Q2.3 R33.1 | length 47.2
  Top Layer w8: Q2.3@4829.2,3970.43 4830.18,3970.43 4843.12,3983.36 R33.1@4843.12,4011.27
NetQ3_1: Q3.1 R37.2 | length 45.7
  Top Layer w8: R37.2@4962.86,3879.4 4964.55,3881.09 4964.55,3921.97 Q3.1@4966.24,3923.66
NetQ3_3: Q3.3 R34.1 | length 45.4
  Top Layer w8: Q3.3@4981.99,3968.94 4982.97,3968.94 4996.35,3982.31 R34.1@4996.35,4007.82
NetQ4_1: Q4.1 U8.21 | length 304.1
  Bottom Layer w8: Q4.1@4765.45,4330.9 4767.19,4329.16 4795.84,4329.16 4834,4291 4960.14,4291 4960.47,4290.66 5050.62,4290.66 U8.21@5052.24,4292.28
NetQ4_4: Q4.4 U8.20 | length 306.9
  Bottom Layer w8: Q4.4@4765.45,4254.13 4805.44,4254.13 4827.9,4276.59 U8.20@5063,4276.59
NetR3_1: R3.1 U3.24 | length 81.7
  Top Layer w8: R3.1@3889.53,2443.7 3890.03,2444.19 3924.82,2444.19 v1(3925.32,2444.68)
  Bottom Layer w8: v1(3925.32,2444.68) U3.24@3970.83,2444.68
NetR4_2: R4.2 U3.26 | length 75.7
  Top Layer w8: R4.2@3896.65,2485 3897.82,2483.83 3927.99,2483.83 v1(3929.16,2482.67)
  Bottom Layer w8: v1(3929.16,2482.67) 3930.12,2483.63 3970.4,2483.63 U3.26@3970.83,2484.06
NetR6_2: R6.2 U3.9 | length 109
  Top Layer w8: v1(4340.24,2404.47) 4343.45,2404.47 4353.71,2414.73 4370.66,2414.73 4372.58,2412.82 4372.58,2409.82 R6.2@4377.49,2414.73
  Bottom Layer w8: U3.9@4279.25,2405.4 4279.6,2405.74 4338.97,2405.74 v1(4340.24,2404.47)
NetR7_2: R7.2 U3.10 | length 101.7
  Top Layer w8: v1(4339.29,2374.98) R7.2@4376.42,2375.01
  Bottom Layer w8: U3.10@4279.17,2385.63 4309.37,2385.63 4316.96,2378.04 4336.23,2378.04 v1(4339.29,2374.98)
NetR8_2: R8.2 U3.11 | length 113.5
  Top Layer w8: v1(4342.75,2329.17) 4343.98,2330.4 4375.19,2330.4 R8.2@4376.42,2331.64
  Bottom Layer w8: U3.11@4279.17,2365.94 4303.59,2365.94 4340.37,2329.17 v1(4342.75,2329.17)
NetR9_1: R9.1 Y1.1 | length 54.6
  Top Layer w8: Y1.1@4532.45,2360 4534.03,2361.58 R9.1@4586.43,2361.58
NetR24_1: R24.1 U6.7 | length 62.4
  Top Layer w8: U6.7@4610.65,2791.92 4610.98,2791.58 4671.78,2791.58 R24.1@4672.55,2790.82
NetR59_1: R59.1 U9.4 | length 84.9
  Top Layer w8: v1(4884.31,4612.69) 4887.38,4615.75 4887.38,4621.63 4910,4644.25 R59.1@4910,4645.24
  Bottom Layer w8: U9.4@4873.49,4575.43 4874.49,4576.43 4874.49,4598.53 4884.31,4608.36 v1(4884.31,4612.69)
NetR60_1: R60.1 R66.2 U9.1 | length 118.3
  Top Layer w8: v1(4793.45,4610.38) 4775.84,4627.99 4775.84,4639.39 R66.2@4770,4645.24 R60.1@4805,4645.24
  Bottom Layer w8: v1(4793.45,4610.38) 4793.45,4606.05 4801.62,4597.88 4801.62,4576.43 U9.1@4802.62,4575.43
NetR64_2: R64.2 U9.2 | length 76.1
  Top Layer w8: v1(4825.57,4608.16) 4827.91,4610.5 4827.91,4632.16 4840,4644.25 R64.2@4840,4645.24
  Bottom Layer w8: v1(4825.57,4608.16) 4825.9,4607.82 4825.9,4575.77 U9.2@4826.24,4575.43
NetR65_2: R65.2 U9.3 | length 69.7
  Top Layer w8: v1(4854.2,4615.28) 4857.26,4618.34 4857.26,4626.51 4875,4644.25 R65.2@4875,4645.24
  Bottom Layer w8: U9.3@4849.75,4575.54 4849.86,4575.65 v1@4849.86,4606.62
NetR67_2: R67.2 U9.9 | length 51.3
  Bottom Layer w8: U9.9@4897.11,4473.43 4897.11,4462.43 4908.7,4450.84 4924.39,4450.84 R67.2@4930.24,4445
NetR68_2: R68.2 U9.11 | length 69.9
  Bottom Layer w8: U9.11@4849.86,4473.43 4850.47,4472.82 4850.47,4439.69 4862.26,4427.9 4862.26,4412.5 R68.2@4865,4409.76
NetR69_2: R69.2 U9.12 | length 63.9
  Bottom Layer w8: R69.2@4825,4410 4825.62,4410.62 4825.62,4472.81 U9.12@4826.24,4473.43
NetR75_2: R75.2 R84.2 U10.32 | length 259
  Top Layer w8: v1(3440,4210) 3470,4210 3503.67,4176.33 3517.97,4176.33 R75.2@3525.78,4168.52
  Bottom Layer w8: U10.32@3386.65,4200 3386.65,4206.82 3387.57,4207.74 3437.74,4207.74 v1(3440,4210) 3444.33,4210 3449.88,4215.55 3452.39,4215.55 3482.65,4245.81 3482.65,4279.32 R84.2@3485.17,4281.84
NetR76_1: R76.1 R81.2 U10.29 | length 312.8
  Top Layer w8: v1(3335.8,4255.28) 3335.8,4259.61 3341.78,4265.6 3341.78,4267.23 3368.32,4293.77 3518.86,4293.77 R76.1@3525.35,4300.25
  Bottom Layer w8: U10.29@3327.6,4200 3327.6,4242.75 3335.8,4250.95 3335.8,4259.04 3362.97,4286.21 R81.2@3362.97,4286.51
NetR78_1: R78.1 R82.2 U10.30 | length 268.1
  Top Layer w8: v1(3385,4260) 3387.4,4262.4 3518.2,4262.4 R78.1@3525.35,4255.25
  Bottom Layer w8: U10.30@3347.28,4200 3347.28,4236.36 3367.86,4256.94 3381.94,4256.94 3388.06,4263.06 3398.06,4263.06 3399.67,4264.67 3399.67,4279.69 R82.2@3405.52,4285.54
NetR79_1: R79.1 R83.2 U10.31 | length 270.7
  Top Layer w8: v1(3405,4235) 3406.09,4236.09 3473.91,4236.09 3500.04,4209.96 R79.1@3524.32,4209.96
  Bottom Layer w8: U10.31@3366.97,4200 3366.97,4229.61 3371.65,4234.3 v1@3403.46,4234.3 ; v1(3405,4235) 3409.33,4235 3415.08,4240.75 3417.19,4240.75 3438.54,4262.1 3438.54,4280.27 R83.2@3445,4286.73
NetU3_22: U3.22
NetU3_23: U3.23
NetU3_25: U3.25
NetU5_23: U5.23
P_RX: U5.36
P_TX: U5.37
PD_ADC1: R48.1 R52.2 U8.2 | length 184.1
  Top Layer w8: R48.1@5304.76,4360 v1(5330,4360)
  Bottom Layer w8: U8.2@5220.48,4323.83 5248.83,4323.83 5285,4360 v1(5330,4360) 5332.08,4360 5342.08,4370 R52.2@5360.24,4370
PD_ADC2: R49.1 R53.2 U8.3 | length 169.9
  Top Layer w8: R49.1@5304.76,4320 v1(5330,4320)
  Bottom Layer w8: U8.3@5220.48,4308.09 5255.28,4308.09 5267.19,4320 v1(5330,4320) R53.2@5360.24,4320
PD_ADC3: R50.1 R54.2 U8.5 | length 178.9
  Top Layer w8: R50.1@5304.5,4257.03 5306.53,4255 5321.21,4255 v1(5323.24,4252.97)
  Bottom Layer w8: U8.5@5220.48,4276.59 5250.6,4276.59 5258.51,4268.69 5281.38,4268.69 5293.04,4257.03 v1@5323.24,4257.03 ; v1(5323.24,4252.97) v1@5323.24,4257.03 ; R54.2@5351.24,4257.03 5347.24,4253.03 5327.24,4253.03 v1@5323.24,4257.03 ; R54.2@5351.28,4257.03 5359.25,4265 R54.2@5360.24,4265
PD_ADC4: R51.1 R55.2 U8.7 | length 180.7
  Top Layer w8: R51.1@5304.76,4215 5307.28,4212.48 5328.03,4212.48 v1(5330.55,4209.97)
  Bottom Layer w8: U8.7@5220.48,4245.09 5220.55,4245.03 5237.64,4245.03 5267.8,4214.87 5302.55,4214.87 5306.55,4210.87 5329.65,4210.87 v1(5330.55,4209.97) ; v1@5332.98,4212.44 5357.8,4212.44 R55.2@5360.24,4210
PD_OK: R31.2 R36.1 U8.31 | length 800.9
  Top Layer w8: R31.2@4843.91,3833.9 4843.91,3874.2 4851.05,3881.35 4885.37,3881.35 v1(4886.99,3882.97)
  Signal Inner w8: v1(4886.99,3882.97) 4890.05,3886.03 4890.05,3894.45 4891.26,3895.66 4891.26,3975.88 4932.73,4017.34 4932.73,4040.01 5031.64,4138.93 5031.64,4214 5047.38,4229.73 5047.38,4292.38 5145.49,4390.49 5185.17,4390.49 5187.03,4392.36 5195.26,4392.36 v1(5198.32,4395.42)
  Bottom Layer w8: U8.31@5181.11,4363.2 5181.18,4363.27 5181.18,4387.03 5184.11,4389.97 5184.64,4389.97 5187.03,4392.36 5195.26,4392.36 v1(5198.32,4395.42)
PG: IC1.18 R43.1 | length 64.3
  Bottom Layer w8: R43.1@4910,3779.76 4910,3779.08 4915.84,3773.24 IC1.18@4971.19,3773.24
PG_ESP: R80.1 TP39.1 U5.19 U10.1 | length 953.6
  Top Layer w16: TP39.1@4052.79,3829.84 4056.57,3833.63 4102.12,3833.63 4105,3830.75 R80.1@4105,3829.76 ; R80.1@4104.47,3831.28 4104.47,3899.31 4103.94,3899.84 4105.01,3900.92 4105.01,3958.06 v1(4106.09,3959.14)
  Signal Inner w8: v1(3439.46,3999.1) 3440.69,3997.87 3440.69,3982.39 3473.82,3949.27 4093.4,3949.27 4103.27,3959.14 v1(4106.09,3959.14)
  Bottom Layer w8: U10.1@3386.65,4011.02 3387.57,4010.1 3387.57,3998.96 3392.26,3994.28 3430.3,3994.28 3435.13,3999.1 v1(3439.46,3999.1)
PLUG_FLIP: U8.13
PWM: J2.4 R27.1 TP27.1 U7.4 | length 316.1
  Top Layer w16: J2.4@2935,2195 3096.02,2195 3115.45,2175.57 TP27.1@3123.9,2175.57 3123.9,2167.12 3110.95,2154.17 R27.1@3110.95,2115.68 3110.95,2073.17 3109.95,2072.17 U7.4@3100.02,2072.17
RES1: R58.2 U8.30 | length 84.4
  Top Layer w8: R58.2@5170.61,4444.02 5171.49,4443.13 5171.49,4414.01 v1(5172.37,4413.13)
  Bottom Layer w8: U8.30@5165.37,4363.2 5165.37,4399.28 5169.31,4403.22 5169.31,4410.07 v1(5172.37,4413.13)
RES2: R57.2 U8.22 | length 59
  Bottom Layer w8: R57.2@5004.76,4310 5006.61,4308.15 5062.94,4308.15 U8.22@5063,4308.09
RES3: R56.2 U8.23 | length 67
  Bottom Layer w8: R56.2@5004.76,4345 5005.75,4345 5026.91,4323.83 U8.23@5063,4323.83
RESET#: C18.2 R21.1 U5.3 | length 124.6
  Top Layer w10: R21.1@3714.79,4486.8 3721.94,4493.95 3764.3,4493.95 C18.2@3765.21,4493.04 ; C18.2@3765.82,4493.65 3829.05,4493.65 U5.3@3834.45,4499.06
